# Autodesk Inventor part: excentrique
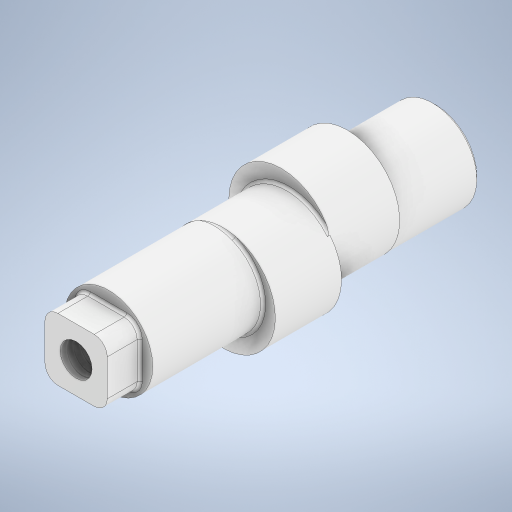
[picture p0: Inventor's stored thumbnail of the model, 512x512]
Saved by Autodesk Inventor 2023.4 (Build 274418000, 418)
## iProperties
Created: 2025-06
Part Number: excentrique
Material: Steel
Document SubType Name: Modeling
Designer: mel
Density: 7.85 g/cm^3
Appearance: Par défaut
Author: mel
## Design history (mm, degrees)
feature "Shaft"
sketch "Esquisse1"
  geometry: C1 r 3.4 at (0, 0) reference; 1 further point
extrude "Extrusion1" join sketch "Esquisse1" distance "d0" = 2; taper "d2" = 0 deg; dims "d1" = 1, "d3" = 0
sketch "Esquisse2"
  geometry: L1 (2.4, 2.4)-(-2.4, 2.4); L2 (-2.4, 2.4)-(-2.4, -2.4); L3 (-2.4, -2.4)-(2.4, -2.4); L4 (2.4, -2.4)-(2.4, 2.4); C1 r 3.4 at (0, 0) reference; 1 further point
  constraints: 8 end point, 2 parallel, 1 horizontal, 1 perpendicular
  dimensions: "d4" = 2.4 distance from line of L4 C1.centre; "d5" = 2.4 distance from line of L1 C1.centre (= d4); "d6" = 2.4 distance from line of C1.centre L2 (= d5); "d7" = 2.4 distance from line of C1.centre L3 (= d5); "d8" = 6.8 diameter of C1 (derived)
extrude "Extrusion2" join sketch "Esquisse2" distance "d9" = 2.5; taper "d10" = 0 deg
sketch "Esquisse3"
  geometry: C1 r 3.4 at (0, 0) reference; 1 further point
hole "Perçage1" sketch "Esquisse3" at (0, 0) diameter "d11" = 2.459; stored, may be unused: countersink angle "d15" = 90 deg, drill point angle "d17" = 118 deg; dims "d12" = 6, "d13" = 4, "d14" = 2, "d16" = 8.8
fillet "Congé1" dims "d18" = 1
fillet "Congé2" dims "d19" = 0.2
sketch "Esquisse4"
  geometry: C1 r 3.15 at (0, 0) reference; 1 further point
extrude "Extrusion3" join sketch "Esquisse4" stored distance "d20" = 2.5; taper "d21" = 0 deg
node "Solide1"
